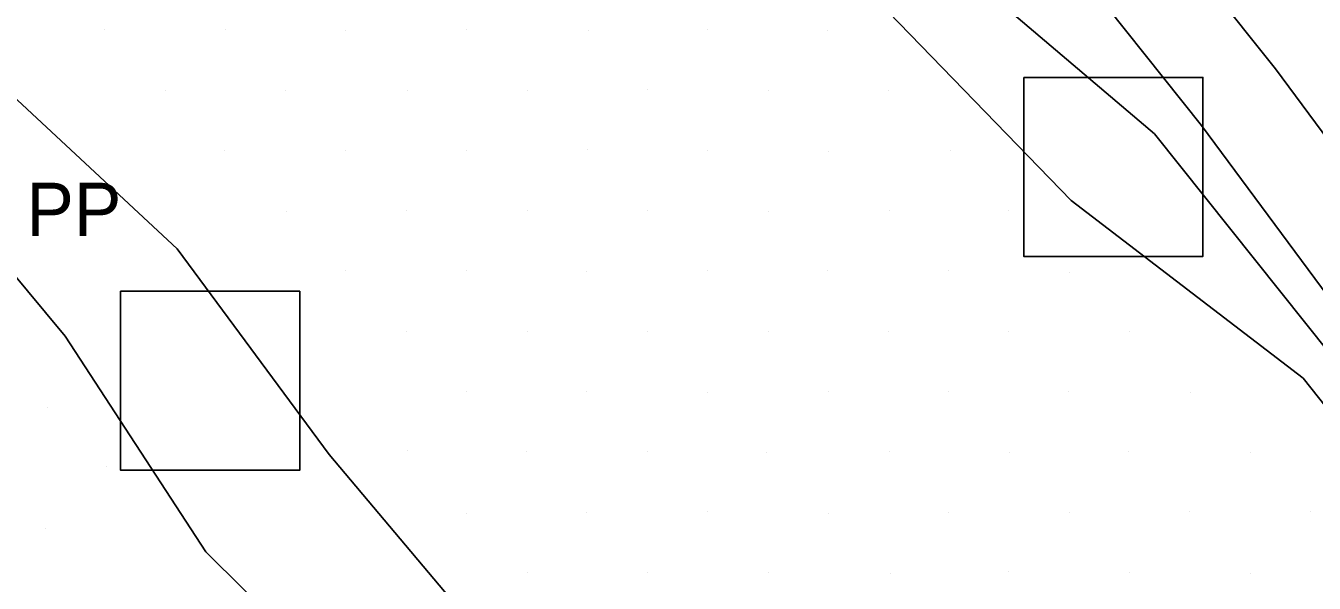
# Model space of a CAD drawing. Extents: x 1602514 to 1609837, y 863887 to 871157.
# Drawn here: x 1605724.3 to 1605875.4, y 867056.2 to 867121.6 of the extents above; entities that cross this region are included whole.
import ezdxf

# ---------------------------------------------------------------- set-up
doc = ezdxf.new("R2010")
doc.units = 0
for name, color, linetype in [('Survey-Centerline', 7, 'Continuous'), ('Survey-Edge of pavement', 7, 'Continuous'), ('Survey-Ridge Lines', 7, 'Continuous'), ('Survey-Spot dirt', 7, 'Continuous'), ('Utility-Pole', 7, 'Continuous')]:
    doc.layers.add(name, color=color, linetype=linetype)

msp = doc.modelspace()

# ---------------------------------------------------------------- linework, layer by layer
at = {"layer": 'Survey-Centerline'}
msp.add_lwpolyline([(1605580.62, 867491.73), (1605596.18, 867472.18), (1605611.44, 867452.4), (1605626.69, 867432.61), (1605641.83, 867412.73), (1605657.05, 867392.92), (1605672.17, 867373.04), (1605687.2, 867353.08), (1605702.52, 867333.34), (1605717.5, 867313.38), (1605732.67, 867293.56), (1605747.89, 867273.79), (1605763.21, 867254.09), (1605778.53, 867234.39), (1605793.95, 867214.77), (1605809.42, 867195.18), (1605824.56, 867175.35), (1605839.7, 867155.51), (1605855.32, 867136.04), (1605870.86, 867116.51), (1605885.73, 867096.47)], dxfattribs=at)
msp.add_lwpolyline([(1605580.62, 867491.73), (1605596.18, 867472.18), (1605611.44, 867452.4), (1605626.69, 867432.61), (1605641.83, 867412.73), (1605657.05, 867392.92), (1605672.17, 867373.04), (1605687.2, 867353.08), (1605702.52, 867333.34), (1605717.5, 867313.38), (1605732.67, 867293.56), (1605747.89, 867273.79), (1605763.21, 867254.09), (1605778.53, 867234.39), (1605793.95, 867214.77), (1605809.42, 867195.18), (1605824.56, 867175.35), (1605839.7, 867155.51), (1605855.32, 867136.04), (1605870.86, 867116.51), (1605885.73, 867096.47)], dxfattribs=at)
at = {"layer": 'Survey-Edge of pavement'}
msp.add_lwpolyline([(1605572.42, 867485.41), (1605587.71, 867465.64), (1605602.98, 867445.87), (1605618.22, 867426.07), (1605633.02, 867405.94), (1605648.49, 867386.32), (1605663.62, 867366.43), (1605678.64, 867346.47), (1605693.94, 867326.76), (1605708.93, 867306.81), (1605724.09, 867286.99), (1605739.31, 867267.21), (1605754.63, 867247.51), (1605770.2, 867228), (1605785.62, 867208.38), (1605800.74, 867188.53), (1605815.88, 867168.7), (1605831.03, 867148.86), (1605846.65, 867129.39), (1605862.19, 867109.86), (1605877.05, 867089.81)], dxfattribs=at)
msp.add_lwpolyline([(1605572.42, 867485.41), (1605587.71, 867465.64), (1605602.98, 867445.87), (1605618.22, 867426.07), (1605633.02, 867405.94), (1605648.49, 867386.32), (1605663.62, 867366.43), (1605678.64, 867346.47), (1605693.94, 867326.76), (1605708.93, 867306.81), (1605724.09, 867286.99), (1605739.31, 867267.21), (1605754.63, 867247.51), (1605770.2, 867228), (1605785.62, 867208.38), (1605800.74, 867188.53), (1605815.88, 867168.7), (1605831.03, 867148.86), (1605846.65, 867129.39), (1605862.19, 867109.86), (1605877.05, 867089.81)], dxfattribs=at)
at = {"layer": 'Survey-Ridge Lines'}
for points in [[(1605697.76, 867314.34), (1605715.34, 867286.06), (1605736.85, 867264.84), (1605749.67, 867248.44), (1605762.89, 867230.84), (1605774.96, 867215.14), (1605787.98, 867195.05), (1605801.92, 867179.25), (1605815.36, 867152.68), (1605832.93, 867129.08), (1605856.69, 867108.88), (1605877.36, 867082.98), (1605887.69, 867069.34), (1605897.39, 867057.19), (1605905.23, 867045.98), (1605917.74, 867022.94), (1605924.28, 867008.81)], [(1605697.76, 867314.34), (1605715.34, 867286.06), (1605736.85, 867264.84), (1605749.67, 867248.44), (1605762.89, 867230.84), (1605774.96, 867215.14), (1605787.98, 867195.05), (1605801.92, 867179.25), (1605815.36, 867152.68), (1605832.93, 867129.08), (1605856.69, 867108.88), (1605877.36, 867082.98), (1605887.69, 867069.34), (1605897.39, 867057.19), (1605905.23, 867045.98), (1605917.74, 867022.94), (1605924.28, 867008.81)], [(1605689.59, 867308.58), (1605698.27, 867273.61), (1605716.21, 867252.4), (1605732.08, 867235.2), (1605745.91, 867217.64), (1605758.06, 867203.01), (1605774.53, 867185.29), (1605783.33, 867165.15), (1605804.9, 867144.51), (1605825.46, 867123.17), (1605846.89, 867101.06), (1605874.11, 867080.26), (1605884.59, 867067.04)], [(1605689.59, 867308.58), (1605698.27, 867273.61), (1605716.21, 867252.4), (1605732.08, 867235.2), (1605745.91, 867217.64), (1605758.06, 867203.01), (1605774.53, 867185.29), (1605783.33, 867165.15), (1605804.9, 867144.51), (1605825.46, 867123.17), (1605846.89, 867101.06), (1605874.11, 867080.26), (1605884.59, 867067.04)], [(1605582.66, 867280.48), (1605587.36, 867276.93), (1605595.5, 867274.75), (1605598.26, 867267.54), (1605604.5, 867266.27), (1605618.86, 867258.75), (1605628.59, 867222.83), (1605638.95, 867205.87), (1605646.2, 867201.28), (1605663.11, 867183.27), (1605676.55, 867163.72), (1605686.84, 867151.89), (1605703.23, 867133.53), (1605719.25, 867116.56), (1605742.01, 867095.41), (1605759.85, 867071.29), (1605779.85, 867047.57)], [(1605582.66, 867280.48), (1605587.36, 867276.93), (1605595.5, 867274.75), (1605598.26, 867267.54), (1605604.5, 867266.27), (1605618.86, 867258.75), (1605628.59, 867222.83), (1605638.95, 867205.87), (1605646.2, 867201.28), (1605663.11, 867183.27), (1605676.55, 867163.72), (1605686.84, 867151.89), (1605703.23, 867133.53), (1605719.25, 867116.56), (1605742.01, 867095.41), (1605759.85, 867071.29), (1605779.85, 867047.57)], [(1605717.72, 867098.59), (1605728.88, 867085.17), (1605745.4, 867059.86), (1605767.63, 867037.82), (1605792.25, 867011.68), (1605817.96, 866986.88), (1605824.65, 866981.38), (1605830.09, 866975.09), (1605834, 866969.61), (1605845.4, 866960.25), (1605862.12, 866943.54), (1605873.66, 866931.56), (1605889.47, 866914.73), (1605907.68, 866900.68), (1605923.23, 866883.18), (1605938.78, 866875.46), (1605942.37, 866867.59), (1605944.68, 866852.25), (1605962.24, 866837.75)], [(1605717.72, 867098.59), (1605728.88, 867085.17), (1605745.4, 867059.86), (1605767.63, 867037.82), (1605792.25, 867011.68), (1605817.96, 866986.88), (1605824.65, 866981.38), (1605830.09, 866975.09), (1605834, 866969.61), (1605845.4, 866960.25), (1605862.12, 866943.54), (1605873.66, 866931.56), (1605889.47, 866914.73), (1605907.68, 866900.68), (1605923.23, 866883.18), (1605938.78, 866875.46), (1605942.37, 866867.59), (1605944.68, 866852.25), (1605962.24, 866837.75)]]:
    msp.add_lwpolyline(points, dxfattribs=at)
at = {"layer": 'Survey-Spot dirt'}
for p, q in [((1605733.53, 867121.11), (1605733.53, 867121.11)), ((1605733.53, 867121.11), (1605733.53, 867121.11)), ((1605747.7, 867121.14), (1605747.7, 867121.14)), ((1605747.7, 867121.14), (1605747.7, 867121.14)), ((1605761.79, 867121.07), (1605761.79, 867121.07)), ((1605761.79, 867121.07), (1605761.79, 867121.07)), ((1605775.91, 867121.11), (1605775.91, 867121.11)), ((1605775.91, 867121.11), (1605775.91, 867121.11)), ((1605790.3, 867121.01), (1605790.3, 867121.01)), ((1605790.3, 867121.01), (1605790.3, 867121.01)), ((1605804.21, 867121.09), (1605804.21, 867121.09)), ((1605804.21, 867121.09), (1605804.21, 867121.09)), ((1605818.32, 867121.02), (1605818.32, 867121.02)), ((1605818.32, 867121.02), (1605818.32, 867121.02)), ((1605740.66, 867114.03), (1605740.66, 867114.03)), ((1605740.66, 867114.03), (1605740.66, 867114.03)), ((1605754.76, 867113.94), (1605754.76, 867113.94)), ((1605754.76, 867113.94), (1605754.76, 867113.94)), ((1605768.99, 867113.98), (1605768.99, 867113.98)), ((1605768.99, 867113.98), (1605768.99, 867113.98)), ((1605783.1, 867113.96), (1605783.1, 867113.96)), ((1605783.1, 867113.96), (1605783.1, 867113.96)), ((1605797.19, 867114.04), (1605797.19, 867114.04)), ((1605797.19, 867114.04), (1605797.19, 867114.04)), ((1605811.38, 867113.92), (1605811.38, 867113.92)), ((1605811.38, 867113.92), (1605811.38, 867113.92)), ((1605825.46, 867114), (1605825.46, 867114)), ((1605825.46, 867114), (1605825.46, 867114)), ((1605747.57, 867106.97), (1605747.57, 867106.97)), ((1605747.57, 867106.97), (1605747.57, 867106.97)), ((1605761.75, 867106.99), (1605761.75, 867106.99)), ((1605761.75, 867106.99), (1605761.75, 867106.99)), ((1605775.92, 867106.96), (1605775.92, 867106.96)), ((1605775.92, 867106.96), (1605775.92, 867106.96)), ((1605790.13, 867107.04), (1605790.13, 867107.04)), ((1605790.13, 867107.04), (1605790.13, 867107.04)), ((1605804.28, 867106.91), (1605804.28, 867106.91)), ((1605804.28, 867106.91), (1605804.28, 867106.91)), ((1605818.44, 867106.87), (1605818.44, 867106.87)), ((1605818.44, 867106.87), (1605818.44, 867106.87)), ((1605832.69, 867106.98), (1605832.69, 867106.98)), ((1605832.69, 867106.98), (1605832.69, 867106.98)), ((1605754.84, 867099.79), (1605754.84, 867099.79)), ((1605754.84, 867099.79), (1605754.84, 867099.79)), ((1605768.9, 867099.9), (1605768.9, 867099.9)), ((1605768.9, 867099.9), (1605768.9, 867099.9)), ((1605783.12, 867099.95), (1605783.12, 867099.95)), ((1605783.12, 867099.95), (1605783.12, 867099.95)), ((1605797.2, 867099.95), (1605797.2, 867099.95)), ((1605797.2, 867099.95), (1605797.2, 867099.95)), ((1605811.39, 867099.84), (1605811.39, 867099.84)), ((1605811.39, 867099.84), (1605811.39, 867099.84)), ((1605825.55, 867099.85), (1605825.55, 867099.85)), ((1605825.55, 867099.85), (1605825.55, 867099.85)), ((1605839.51, 867099.91), (1605839.51, 867099.91)), ((1605839.51, 867099.91), (1605839.51, 867099.91)), ((1605761.78, 867092.83), (1605761.78, 867092.83)), ((1605761.78, 867092.83), (1605761.78, 867092.83)), ((1605775.95, 867092.82), (1605775.95, 867092.82)), ((1605775.95, 867092.82), (1605775.95, 867092.82)), ((1605790.09, 867092.77), (1605790.09, 867092.77)), ((1605790.09, 867092.77), (1605790.09, 867092.77)), ((1605804.25, 867092.9), (1605804.25, 867092.9)), ((1605804.25, 867092.9), (1605804.25, 867092.9)), ((1605818.28, 867092.91), (1605818.28, 867092.91)), ((1605818.28, 867092.91), (1605818.28, 867092.91)), ((1605832.52, 867092.84), (1605832.52, 867092.84)), ((1605832.52, 867092.84), (1605832.52, 867092.84)), ((1605846.75, 867092.66), (1605846.75, 867092.66)), ((1605846.75, 867092.66), (1605846.75, 867092.66)), ((1605768.91, 867085.71), (1605768.91, 867085.71)), ((1605768.91, 867085.71), (1605768.91, 867085.71)), ((1605783.11, 867085.74), (1605783.11, 867085.74)), ((1605783.11, 867085.74), (1605783.11, 867085.74)), ((1605797.15, 867085.73), (1605797.15, 867085.73)), ((1605797.15, 867085.73), (1605797.15, 867085.73)), ((1605811.37, 867085.67), (1605811.37, 867085.67)), ((1605811.37, 867085.67), (1605811.37, 867085.67)), ((1605825.45, 867085.76), (1605825.45, 867085.76)), ((1605825.45, 867085.76), (1605825.45, 867085.76)), ((1605839.55, 867085.72), (1605839.55, 867085.72)), ((1605839.55, 867085.72), (1605839.55, 867085.72)), ((1605853.74, 867085.74), (1605853.74, 867085.74)), ((1605853.74, 867085.74), (1605853.74, 867085.74)), ((1605775.99, 867078.67), (1605775.99, 867078.67)), ((1605775.99, 867078.67), (1605775.99, 867078.67)), ((1605790.08, 867078.68), (1605790.08, 867078.68)), ((1605790.08, 867078.68), (1605790.08, 867078.68)), ((1605804.26, 867078.57), (1605804.26, 867078.57)), ((1605804.26, 867078.57), (1605804.26, 867078.57)), ((1605818.42, 867078.65), (1605818.42, 867078.65)), ((1605818.42, 867078.65), (1605818.42, 867078.65)), ((1605832.54, 867078.67), (1605832.54, 867078.67)), ((1605832.54, 867078.67), (1605832.54, 867078.67)), ((1605846.59, 867078.73), (1605846.59, 867078.73)), ((1605846.59, 867078.73), (1605846.59, 867078.73)), ((1605860.9, 867078.57), (1605860.9, 867078.57)), ((1605860.9, 867078.57), (1605860.9, 867078.57)), ((1605726.76, 867076.86), (1605726.76, 867076.86)), ((1605726.76, 867076.86), (1605726.76, 867076.86)), ((1605769.01, 867071.72), (1605769.01, 867071.72)), ((1605769.01, 867071.72), (1605769.01, 867071.72)), ((1605783.05, 867071.61), (1605783.05, 867071.61)), ((1605783.05, 867071.61), (1605783.05, 867071.61)), ((1605797.15, 867071.61), (1605797.15, 867071.61)), ((1605797.15, 867071.61), (1605797.15, 867071.61)), ((1605811.21, 867071.57), (1605811.21, 867071.57)), ((1605811.21, 867071.57), (1605811.21, 867071.57)), ((1605825.55, 867071.59), (1605825.55, 867071.59)), ((1605825.55, 867071.59), (1605825.55, 867071.59)), ((1605839.65, 867071.54), (1605839.65, 867071.54)), ((1605839.65, 867071.54), (1605839.65, 867071.54)), ((1605853.68, 867071.64), (1605853.68, 867071.64)), ((1605853.68, 867071.64), (1605853.68, 867071.64)), ((1605867.99, 867071.49), (1605867.99, 867071.49)), ((1605867.99, 867071.49), (1605867.99, 867071.49)), ((1605733.7, 867069.88), (1605733.7, 867069.88)), ((1605733.7, 867069.88), (1605733.7, 867069.88)), ((1605775.97, 867064.43), (1605775.97, 867064.43)), ((1605775.97, 867064.43), (1605775.97, 867064.43)), ((1605790.08, 867064.51), (1605790.08, 867064.51)), ((1605790.08, 867064.51), (1605790.08, 867064.51)), ((1605804.27, 867064.55), (1605804.27, 867064.55)), ((1605804.27, 867064.55), (1605804.27, 867064.55)), ((1605818.38, 867064.37), (1605818.38, 867064.37)), ((1605818.38, 867064.37), (1605818.38, 867064.37)), ((1605832.52, 867064.54), (1605832.52, 867064.54)), ((1605832.52, 867064.54), (1605832.52, 867064.54)), ((1605846.65, 867064.53), (1605846.65, 867064.53)), ((1605846.65, 867064.53), (1605846.65, 867064.53)), ((1605860.76, 867064.55), (1605860.76, 867064.55)), ((1605860.76, 867064.55), (1605860.76, 867064.55)), ((1605874.98, 867064.55), (1605874.98, 867064.55)), ((1605874.98, 867064.55), (1605874.98, 867064.55)), ((1605726.6, 867062.58), (1605726.6, 867062.58)), ((1605726.6, 867062.58), (1605726.6, 867062.58)), ((1605783.16, 867057.44), (1605783.16, 867057.44)), ((1605783.16, 867057.44), (1605783.16, 867057.44)), ((1605797.16, 867057.48), (1605797.16, 867057.48)), ((1605797.16, 867057.48), (1605797.16, 867057.48)), ((1605811.37, 867057.48), (1605811.37, 867057.48)), ((1605811.37, 867057.48), (1605811.37, 867057.48)), ((1605825.72, 867057.33), (1605825.72, 867057.33)), ((1605825.72, 867057.33), (1605825.72, 867057.33)), ((1605839.57, 867057.53), (1605839.57, 867057.53)), ((1605839.57, 867057.53), (1605839.57, 867057.53)), ((1605853.73, 867057.48), (1605853.73, 867057.48)), ((1605853.73, 867057.48), (1605853.73, 867057.48)), ((1605867.93, 867057.32), (1605867.93, 867057.32)), ((1605867.93, 867057.32), (1605867.93, 867057.32))]:
    msp.add_line(p, q, dxfattribs=at)
at = {"layer": 'Utility-Pole'}
for points in [[(1605841.35, 867115.52), (1605862.35, 867115.52), (1605862.35, 867094.52), (1605841.35, 867094.52)], [(1605841.35, 867115.52), (1605862.35, 867115.52), (1605862.35, 867094.52), (1605841.35, 867094.52)], [(1605735.39, 867090.44), (1605756.4, 867090.44), (1605756.4, 867069.44), (1605735.39, 867069.44)], [(1605735.39, 867090.44), (1605756.4, 867090.44), (1605756.4, 867069.44), (1605735.39, 867069.44)]]:
    msp.add_lwpolyline(points, close=True, dxfattribs=at)

# ---------------------------------------------------------------- texts
msp.add_text('PP', height=6.251, dxfattribs=at).set_placement((1605724.33, 867096.91))
msp.add_text('PP', height=6.251, dxfattribs=at).set_placement((1605724.33, 867096.91))

doc.saveas('drawing.dxf')
